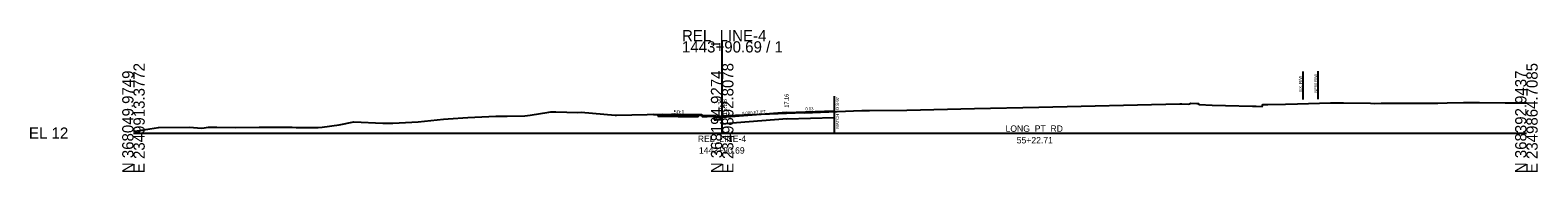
# Model space of a CAD drawing. Extents: x -26 to 2350146, y -10 to 368200.
# Drawn here: x 1974.3 to 2349.2, y 3990.3 to 4025.7 of the extents above; entities that cross this region are included whole.
import ezdxf

# ---------------------------------------------------------------- set-up
doc = ezdxf.new("R2010")
doc.units = 0
for name, color, linetype in [('RD_GPK_XS_Cell', 7, 'Continuous'), ('RD_XS_Base', 7, 'Continuous'), ('RD_XS_CurbBase', 7, 'Continuous'), ('RD_XS_CurbFront', 7, 'Continuous'), ('RD_XS_CurbTop', 7, 'Continuous'), ('RD_XS_EarthShd', 7, 'Continuous'), ('RD_XS_ExGround', 7, 'Continuous'), ('RD_XS_ExRW', 7, 'Continuous'), ('RD_XS_NewRW', 7, 'Continuous'), ('RD_XS_Pave', 7, 'Continuous'), ('RD_XS_SW', 7, 'Continuous'), ('RD_XS_SWbase', 7, 'Continuous'), ('RD_XS_TieSlope', 7, 'Continuous'), ('RD_XS_TX_Elev_EX', 7, 'Continuous'), ('RD_XS_TX_Elev_PR', 7, 'Continuous'), ('RD_XS_TX_MatchLine', 7, 'Continuous'), ('RD_XS_TX_Slope', 7, 'Continuous'), ('RD_XS_TX_Station', 7, 'Continuous'), ('RD_XS_TX_TOC', 7, 'Continuous')]:
    doc.layers.add(name, color=color, linetype=linetype)

msp = doc.modelspace()

# ---------------------------------------------------------------- linework, layer by layer
at = {"layer": 'RD_GPK_XS_Cell'}
for p, q in [((2146.4, 4000), (2146.4, 4022.91)), ((2000, 4000), (2146.4, 4000)), ((2146.4, 4000), (2346.4, 4000))]:
    msp.add_line(p, q, dxfattribs=at)
at = {"layer": 'RD_XS_Base'}
for p, q in [((2174.23, 4005.52), (2174.23, 4003.88)), ((2146.4, 4002.24), (2146.4, 4003.36)), ((2149.94, 4002.52), (2146.4, 4002.24)), ((2162.54, 4003.53), (2149.94, 4002.52)), ((2162.45, 4003.53), (2174.23, 4003.88))]:
    msp.add_line(p, q, dxfattribs=at)
at = {"layer": 'RD_XS_CurbBase'}
for p, q in [((2144.4, 4004.28), (2144.4, 4003.28)), ((2144.4, 4003.28), (2144.9, 4003.28)), ((2144.9, 4003.28), (2146.4, 4003.36)), ((2146.4, 4002.3), (2146.4, 4003.36))]:
    msp.add_line(p, q, dxfattribs=at)
at = {"layer": 'RD_XS_CurbFront'}
msp.add_line((2146.4, 4003.36), (2146.4, 4003.86), dxfattribs=at)
at = {"layer": 'RD_XS_CurbTop'}
for p, q in [((2144.9, 4004.28), (2144.4, 4004.28)), ((2144.99, 4003.78), (2144.9, 4004.28)), ((2146.4, 4003.86), (2144.99, 4003.78)), ((2146.4, 4003.88), (2146.4, 4003.86))]:
    msp.add_line(p, q, dxfattribs=at)
at = {"layer": 'RD_XS_EarthShd'}
for p, q in [((2130.4, 4004.56), (2129.4, 4004.58)), ((2144.4, 4004.28), (2140.4, 4004.36))]:
    msp.add_line(p, q, dxfattribs=at)
at = {"layer": 'RD_XS_ExGround'}
msp.add_lwpolyline([(2000, 4000.5), (2000.96, 4000.58), (2004.11, 4001.07), (2006.24, 4001.41), (2013.88, 4001.52), (2017, 4001.27), (2018.66, 4001.52), (2020.75, 4001.51), (2025.34, 4001.43), (2031.25, 4001.48), (2031.84, 4001.5), (2033.53, 4001.5), (2039.48, 4001.52), (2040.5, 4001.41), (2045.91, 4001.37), (2046.89, 4001.48), (2051.15, 4002.04), (2054.76, 4002.78), (2062.02, 4002.51), (2063.8, 4002.49), (2064.51, 4002.5), (2070.79, 4002.82), (2077.11, 4003.47), (2078.24, 4003.58), (2083.15, 4003.93), (2090.1, 4004.23), (2092.97, 4004.22), (2097.32, 4004.3), (2098.67, 4004.49), (2103.33, 4005.23), (2103.8, 4005.29), (2105, 4005.29), (2110.48, 4005.17), (2111.3, 4005.24), (2119.77, 4004.5), (2120.14, 4004.51), (2131.54, 4004.76), (2133.04, 4004.65), (2133.79, 4004.7), (2134.5, 4004.71), (2134.9, 4004.7), (2138.15, 4004.66), (2140.72, 4004.62), (2141.28, 4004.62), (2141.46, 4004.12), (2142.67, 4004.17), (2143.13, 4004.19), (2144.34, 4004.23), (2146.4, 4004.34), (2147.74, 4004.41), (2149.73, 4004.5), (2153.98, 4004.66), (2164.58, 4005.06), (2165.37, 4005.1), (2166.79, 4005.09), (2181.1, 4005.65), (2183.03, 4005.65), (2192.3, 4005.74), (2209.12, 4006.1), (2225.14, 4006.44), (2260.22, 4007.27), (2260.68, 4007.27), (2262.3, 4007.21), (2262.6, 4007.33), (2262.96, 4007.48), (2264.44, 4007.4), (2264.52, 4007.4), (2264.88, 4007.4), (2265.05, 4007.1), (2268.25, 4006.98), (2271.57, 4006.88), (2278.25, 4006.76), (2279.17, 4006.75), (2280.7, 4006.67), (2280.87, 4007.17), (2281.38, 4007.17), (2282.1, 4007.17), (2286.47, 4007.25), (2289.48, 4007.34), (2297.72, 4007.57), (2300.94, 4007.56), (2307.64, 4007.49), (2308.6, 4007.38), (2310.31, 4007.49), (2316.48, 4007.5), (2317.82, 4007.5), (2324.34, 4007.48), (2326.69, 4007.58), (2330.77, 4007.64), (2334.7, 4007.61), (2341.12, 4007.55), (2344.92, 4007.54), (2346.4, 4007.55)], dxfattribs=at)
at = {"layer": 'RD_XS_ExRW'}
msp.add_line((2290.85, 4008.38), (2290.85, 4015.38), dxfattribs=at)
at = {"layer": 'RD_XS_NewRW'}
msp.add_line((2294.65, 4008.49), (2294.65, 4015.49), dxfattribs=at)
at = {"layer": 'RD_XS_Pave'}
for p, q in [((2174.23, 4009.25), (2174.23, 4000.09)), ((2162.4, 4005.16), (2146.4, 4003.88)), ((2162.4, 4005.16), (2174.23, 4005.52))]:
    msp.add_line(p, q, dxfattribs=at)
at = {"layer": 'RD_XS_SW'}
msp.add_line((2140.4, 4004.36), (2130.4, 4004.56), dxfattribs=at)
at = {"layer": 'RD_XS_SWbase'}
for p, q in [((2130.4, 4004.56), (2130.4, 4004.22)), ((2140.4, 4004.02), (2140.4, 4004.36)), ((2130.4, 4004.22), (2140.4, 4004.02))]:
    msp.add_line(p, q, dxfattribs=at)
at = {"layer": 'RD_XS_TieSlope'}
msp.add_line((2129.4, 4004.58), (2129.14, 4004.71), dxfattribs=at)

# ---------------------------------------------------------------- texts
at = {"layer": 'RD_GPK_XS_Cell'}
for s, p in [('REL_LINE-4', (2136.4, 4022.91)), ('1443+90.69 / 1', (2136.4, 4020.11)), ('EL 12', (1974, 3998.6))]:
    msp.add_text(s, height=2.8, dxfattribs=at).set_placement(p)
for s, p in [('E 2349913.3772', (2002.8, 3990)), ('E 2349892.8078', (2149.2, 3990)), ('E 2349864.7085', (2349.2, 3990)), ('N 368049.9749', (2000, 3990)), ('N 368194.9274', (2146.4, 3990)), ('N 368392.9437', (2346.4, 3990))]:
    msp.add_text(s, height=2.8, rotation=90, dxfattribs=at).set_placement(p)
at = {"layer": 'RD_XS_ExRW'}
msp.add_text('EX. R/W ', height=0.75, rotation=90, dxfattribs=at).set_placement((2290.59, 4010.33))
at = {"layer": 'RD_XS_NewRW'}
msp.add_text('NEW R/W ', height=0.75, rotation=90, dxfattribs=at).set_placement((2294.39, 4010.07))
at = {"layer": 'RD_XS_TX_Elev_EX'}
msp.add_text('16.34', height=1, rotation=90, dxfattribs=at).set_placement((2146.34, 4005.17))
at = {"layer": 'RD_XS_TX_Elev_PR'}
for s, height, rotation, p in [(' 15.88', 1.2, 90, (2147.6, 4003.88)), ('17.16', 1, 90, (2162.9, 4006.35)), ('50:1', 1, 358.8542, (2134.33, 4004.78))]:
    msp.add_text(s, height=height, rotation=rotation, dxfattribs=at).set_placement(p)
at = {"layer": 'RD_XS_TX_MatchLine'}
msp.add_text('MATCH TO S-97', height=0.75, rotation=90, dxfattribs=at).set_placement((2175.42, 4001.13))
at = {"layer": 'RD_XS_TX_Slope'}
for s, rotation, p in [('0.080 FT./FT.', 4.5739, (2151.37, 4004.53)), ('0.03', 1.7184, (2167.1, 4005.64))]:
    msp.add_text(s, height=0.75, rotation=rotation, dxfattribs=at).set_placement(p)
at = {"layer": 'RD_XS_TX_Station'}
for s, p in [('LONG_PT_RD', (2216.87, 4000.32)), ('REL_LINE-4', (2140.34, 3997.78)), ('55+22.71', (2219.66, 3997.42)), ('1443+90.69', (2140.63, 3994.88))]:
    msp.add_text(s, height=1.6, dxfattribs=at).set_placement(p)
at = {"layer": 'RD_XS_TX_TOC'}
msp.add_text('TOCLT', height=0.05, dxfattribs=at).set_placement((2144.95, 4004.23))

doc.saveas('drawing.dxf')
